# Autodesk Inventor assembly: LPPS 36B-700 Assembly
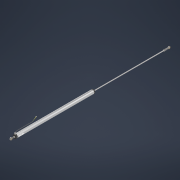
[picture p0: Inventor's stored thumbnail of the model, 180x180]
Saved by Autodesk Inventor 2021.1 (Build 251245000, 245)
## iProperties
Created: 2020-09
Part Number: LPPS 36B-700 Assembly
Document SubType Name: Assembly
Designer: J. Nielson
Author: J. Nielson
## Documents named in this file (3)
- C:\Users\Justin\Documents\CAD\The Sensor Connection\LPPS\LPPS-36B Series\3D\LPPS-36B-700\LPPS 36B-700 Assembly.iam
- C:\Users\Justin\Documents\CAD\The Sensor Connection\LPPS\LPPS-36B Series\3D\LPPS-36B-700\LPPS 36B-700 Shaft_Shrinkwrap.ipt
- C:\Users\Justin\Documents\CAD\The Sensor Connection\LPPS\LPPS-36B Series\3D\LPPS-36B-700\LPPS 36B-700_Shrinkwrap.ipt
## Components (2 placed, 2 different names)
1. LPPS 36B-700 Shaft_Shrinkwrap:1
2. LPPS 36B-700_Shrinkwrap:1
